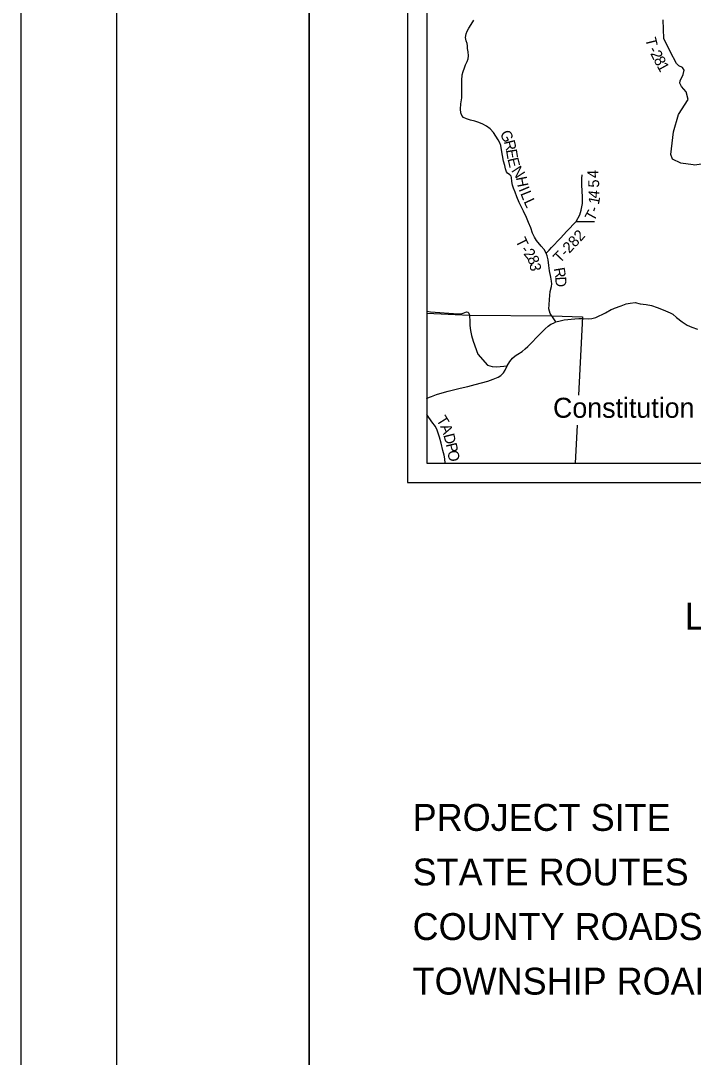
# Model space of a CAD drawing. Extents: x -84548 to 2262448, y -162180 to 525962.
# Drawn here: x 0 to 18466, y 58091 to 86581 of the extents above; entities that cross this region are included whole.
import ezdxf

# ---------------------------------------------------------------- set-up
doc = ezdxf.new("R2010")
doc.units = 0
for name, color, linetype in [('GM_X_Adjacent_County', 7, 'Continuous'), ('GM_X_Adjacent_County_Text', 7, 'Continuous'), ('GM_X_County', 7, 'Continuous'), ('GM_X_Hydro', 7, 'Continuous'), ('GM_X_Minor_Lake', 7, 'Continuous'), ('GM_X_Minor_River_Text', 7, 'Continuous'), ('GM_X_Township', 7, 'Continuous'), ('GM_X_Township_Road', 7, 'Continuous')]:
    doc.layers.add(name, color=color, linetype=linetype)

msp = doc.modelspace()

# ---------------------------------------------------------------- linework, layer by layer
at = {"layer": 'GM_X_Adjacent_County'}
for points in [[(2640, 113520), (7920, 113520), (7920, 2640), (2640, 2640)], [(7920, 113520), (176880, 113520), (176880, 2640), (7920, 2640)]]:
    msp.add_lwpolyline(points, close=True, dxfattribs=at)
at = {"layer": 'GM_X_County'}
for p, q in [((10619, 110849), (10619, 73889)), ((11147, 91128), (11147, 74417)), ((11147, 74417), (47051, 74417)), ((10619, 73889), (47579, 73889))]:
    msp.add_line(p, q, dxfattribs=at)
at = {"layer": 'GM_X_Hydro'}
for p, q in [((11147, 78542), (12320, 78493)), ((12320, 78493), (14579, 78466)), ((14579, 78466), (15424, 78442)), ((15424, 78442), (15317, 76289)), ((15276, 75465), (15224, 74417))]:
    msp.add_line(p, q, dxfattribs=at)
at = {"layer": 'GM_X_Minor_Lake'}
for points in [[(14430, 80193), (14369, 80297), (14288, 80388), (14159, 80541), (14104, 80629), (14053, 80745), (14002, 80891), (13947, 81038), (13886, 81174), (13801, 81344), (13687, 81589), (13624, 81741), (13577, 81865), (13530, 81978), (13503, 82066), (13486, 82162), (13479, 82268), (13463, 82306), (13429, 82344), (13370, 82392), (13334, 82432), (13311, 82509), (13289, 82601), (13256, 82725), (13228, 82877), (13205, 83029), (13180, 83155), (13154, 83229), (13109, 83309), (13050, 83405), (12983, 83506), (12891, 83606), (12786, 83687), (12690, 83742), (12577, 83788), (12465, 83821), (12353, 83846), (12244, 83881), (12162, 83919), (12110, 83974), (12081, 84050), (12074, 84150), (12085, 84293), (12112, 84461), (12114, 84617), (12109, 84777), (12108, 84938), (12125, 85090), (12144, 85184), (12181, 85286), (12214, 85373), (12260, 85459), (12287, 85535), (12299, 85620), (12288, 85724), (12271, 85814), (12268, 85888), (12262, 85956), (12231, 86030), (12217, 86116), (12230, 86220), (12257, 86294), (12305, 86378), (12372, 86475), (12440, 86596)], [(18461, 82619), (18129, 82667), (17901, 82776), (17847, 82907), (17923, 83526), (18064, 84005), (18325, 84418), (18271, 84624), (18140, 84777), (18097, 84864), (18107, 84929), (18194, 85103), (18216, 85222), (18173, 85299), (18075, 85342), (18010, 85407), (17836, 85734), (17662, 86092), (17640, 86603)], [(22493, 81348), (22000, 81384), (22043, 82167), (22032, 82384), (21924, 82450), (21826, 82526), (21826, 82634), (21891, 82732), (21902, 82852), (21837, 83026), (21597, 83330), (21228, 83483), (20706, 83385), (20543, 83341), (20271, 83189), (20043, 83069), (19836, 83004), (19608, 82928), (19456, 82939), (18890, 82667), (18499, 82613), (18468, 82618), (18461, 82619)], [(15247, 81060), (15354, 81243), (15390, 81376), (15421, 81555), (15428, 81730), (15407, 82070), (15406, 82246), (15413, 82349)], [(14430, 80193), (14512, 80276), (14578, 80344), (14824, 80609), (14993, 80798), (15247, 81060), (15758, 81066)], [(14573, 78475), (14536, 78536), (14503, 78662), (14506, 78777), (14521, 78917), (14532, 79026), (14536, 79136), (14575, 79279), (14583, 79349), (14578, 79421), (14555, 79529), (14520, 79705), (14503, 79853), (14479, 80005), (14454, 80121), (14430, 80193)], [(14691, 78305), (14579, 78466), (14573, 78475)], [(11655, 74417), (11648, 74537), (11627, 74641), (11594, 74767), (11547, 74967), (11502, 75137), (11436, 75328), (11385, 75428), (11288, 75559), (11165, 75731), (11147, 75757)]]:
    msp.add_lwpolyline(points, dxfattribs=at)
at = {"layer": 'GM_X_Minor_River_Text'}
for points in [[(15790, 78428), (15862, 78461), (15984, 78515), (16056, 78554), (16212, 78640), (16267, 78664)], [(16267, 78664), (16304, 78681), (16483, 78747), (16626, 78796), (16732, 78817), (16868, 78835), (17013, 78804), (17175, 78783), (17317, 78754), (17473, 78702), (17642, 78637), (17832, 78554), (17902, 78512), (18005, 78426), (18159, 78309), (18302, 78211), (18428, 78158), (18580, 78104)], [(11147, 78600), (11248, 78579), (12013, 78521), (12088, 78523), (12145, 78548), (12239, 78579), (12279, 78575), (12304, 78548), (12320, 78493), (12320, 78444), (12331, 78350), (12333, 78209), (12353, 78070), (12378, 77933), (12425, 77774), (12548, 77417), (12821, 77118), (12941, 77076), (13070, 77068), (13359, 77100)], [(11147, 76202), (11152, 76205), (11276, 76251), (11413, 76306), (11573, 76355), (11739, 76404), (11887, 76440), (12063, 76481), (12278, 76530), (12474, 76583), (12654, 76626), (12824, 76677), (12973, 76726), (13107, 76780), (13185, 76833), (13254, 76899), (13302, 76975), (13359, 77100), (13429, 77216), (13504, 77309), (13576, 77373), (13648, 77418), (13771, 77494), (13855, 77559), (13927, 77625), (14040, 77746), (14161, 77876), (14293, 78007), (14402, 78116), (14482, 78182), (14559, 78237), (14625, 78267), (14691, 78305), (14810, 78334), (14919, 78358), (15216, 78389), (15326, 78396), (15421, 78396), (15581, 78388), (15682, 78398), (15789, 78427), (15790, 78428)]]:
    msp.add_lwpolyline(points, dxfattribs=at)
at = {"layer": 'GM_X_Township'}
msp.add_lwpolyline([(0, 0), (179520, 0), (179520, 116160), (0, 116160)], close=True, dxfattribs=at)

# ---------------------------------------------------------------- texts
at = {"layer": 'GM_X_Adjacent_County_Text'}
msp.add_text('Constitution', height=550, rotation=0, dxfattribs=at).set_placement((14616, 75668))
at = {"layer": 'GM_X_County'}
for s, p in [('LATITUDE: 39° 23\' 34"   LONGITUDE: -81° 33\' 40"', (18233, 69843)), ('PROJECT SITE', (10761, 64314)), ('STATE ROUTES', (10761, 62814)), ('COUNTY ROADS', (10761, 61314)), ('TOWNSHIP ROADS', (10761, 59814))]:
    msp.add_text(s, height=739.2, dxfattribs=at).set_placement(p)
at = {"layer": 'GM_X_Township_Road'}
for s, rotation, p in [('T', 283.6849, (17145, 86082)), ('2', 296.1706, (17283, 85681)), ('-', 297.8062, (17227, 85788)), ('8', 297.7439, (17369, 85508)), ('1', 298.7913, (17458, 85339)), ('G', 298.6704, (13144, 83475)), ('R', 284.0789, (13263, 83262)), ('E', 279.2802, (13322, 83029)), ('E', 283.673, (13363, 82783)), ('N', 303.2894, (13460, 82463)), ('4', 90.5299, (15860, 82259)), ('H', 281.3746, (13594, 82270)), ('5', 89.3103, (15881, 81994)), ('I', 292.874, (13665, 81948)), ('L', 291.8691, (13713, 81836)), ('4', 84.3632, (15874, 81689)), ('L', 294.7798, (13803, 81613)), ('1', 78.8224, (15872, 81511)), ('T', 61.1056, (15734, 81048)), ('-', 72.1691, (15838, 81296)), ('T', 295.7299, (13578, 80539)), ('T-282', 46.7637, (14806, 79899)), ('-', 307.3867, (13710, 80280)), ('2', 309.8199, (13793, 80172)), ('8', 293.311, (13900, 80049)), ('3', 279.0615, (13967, 79898)), ('R', 279.6311, (14635, 79775)), ('D', 273.5613, (14675, 79540)), ('T', 302.0169, (11399, 75610)), ('A', 290.8378, (11512, 75434)), ('D', 284.4053, (11603, 75195)), ('P', 283.5145, (11668, 74941)), ('O', 279.537, (11714, 74750))]:
    msp.add_text(s, height=300, rotation=rotation, dxfattribs=at).set_placement(p)

doc.saveas('drawing.dxf')
